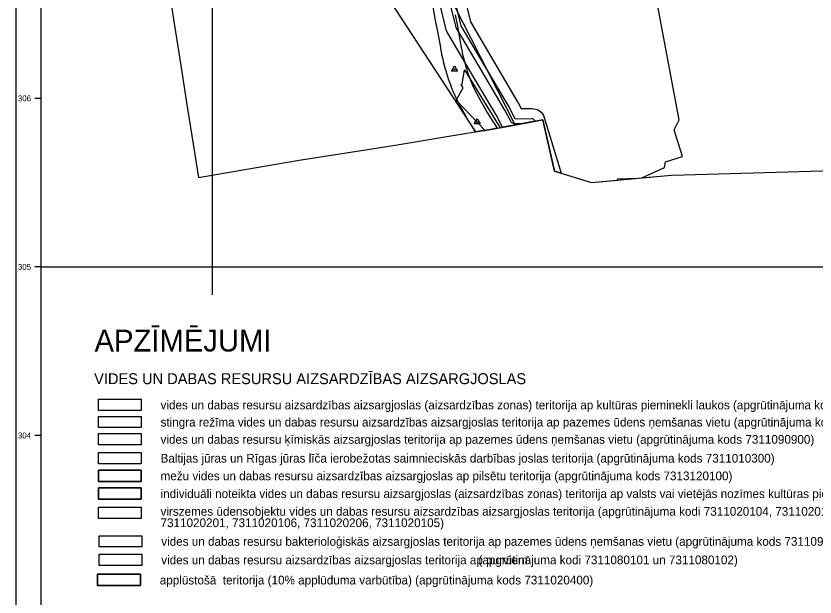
# Model space of a CAD drawing. Extents: x 468834 to 503362, y 294936 to 320859.
# Drawn here: x 468834 to 473572, y 303042 to 306489 of the extents above; entities that cross this region are included whole.
import ezdxf

# ---------------------------------------------------------------- set-up
doc = ezdxf.new("R2010")
doc.units = 0
for name, color, linetype in [('1020108_TIN18_Kemeru_nacionala_parka_teritorija', 7, 'Continuous'), ('7311010300_Baltijas jūras un Rīgas jūras līča ierobežotas saimnieciskās darbības joslas teritorija', 7, 'Continuous'), ('7311020105_dabiskas ūdensteces vides un dabas resursu aizsardzības aizsargjoslas teritorija pilsētās un ciemos', 7, 'Continuous'), ('7311020400_applūstošā (10% applūduma varbūtība) teritorija', 7, 'Continuous'), ('7311080101_vides un dabas resursu aizsardzības aizsargjoslas teritorija ap purvu ar platību no 10 līdz 100 hektāriem', 7, 'Continuous'), ('7311080102_vides un dabas resursu aizsardzības aizsargjoslas teritorija ap purvu ar platību lielāku par 100 hektāriem', 7, 'Continuous'), ('7311090700_stingra režīma vides un dabas resursu aizsardzības aizsargjoslas teritorija ap pazemes ūdens ņemšanas vietu', 7, 'Continuous'), ('7311090800_vides un dabas resursu bakterioloģiskās aizsargjoslas teritorija ap pazemes ūdens ņemšanas vietu', 7, 'Continuous'), ('7311090900_vides un dabas resursu ķīmiskās aizsargjoslas teritorija ap pazemes ūdens ņemšanas vietu', 7, 'Continuous'), ('7312020101_drošības aizsargjoslas teritorija ap gāzesvadu gāzes regulēšanas staciju un gāzes mērīšanas staciju ar gāzesvada diametru līdz 300 milimetriem', 7, 'Continuous'), ('7312030302_ekspluatācijas aizsargjoslas teritorija gar valsts reģionālajiem autoceļiem lauku apvidos', 7, 'Continuous'), ('7312080103_ekspluatācijas aizsargjoslas teritorija gar gāzesvadu ar spiedienu lielāku par 16 megapaskliem', 7, 'Continuous'), ('7313020300_nacionālā parka dabas lieguma zonas teritorija', 7, 'Continuous'), ('7313080100_aizsargājamo ģeoloģisko un ģeomorfoloģisko dabas pieminekļu teritorija', 7, 'Continuous'), ('7313120100_mežu vides un dabas resursu aizsardzības aizsargjoslas ap pilsētu teritorija', 7, 'Continuous'), ('7314020101_vides un dabas resursu aizsardzības aizsargjoslas (aizsardzības zonas) teritorija ap kultūras pieminekli laukos', 7, 'Continuous'), ('7314020201_individuāli noteikta vides un dabas resursu aizsargjoslas (aizsardzības zonas) teritorija ap valsts vai vietējās nozīmes kultūras pieminekli', 7, 'Continuous'), ('aizkrāsjoums-meža aizsargjosla ap pilsētām', 7, 'Continuous'), ('aizkrāsojums_applūstošā teritorija', 7, 'Continuous'), ('Nacionālā parka robeža', 7, 'Continuous'), ('ramis', 7, 'Continuous'), ('Teksts', 7, 'Continuous'), ('Vietējā ģeodēziskā tīkla punkti', 7, 'Continuous')]:
    doc.layers.add(name, color=color, linetype=linetype)

msp = doc.modelspace()

# ---------------------------------------------------------------- linework, layer by layer
at = {"layer": '1020108_TIN18_Kemeru_nacionala_parka_teritorija'}
for p, q in [((469734.9, 306680.4), (469772.2, 306444)), ((469772.2, 306444), (469793.7, 306307.6)), ((469793.7, 306307.6), (469817.3, 306157.4)), ((469817.3, 306157.4), (469845.9, 305976)), ((469845.9, 305976), (469916, 305531.2)), ((471688.4, 305823), (471958.9, 305873.1)), ((471958.9, 305873.1), (472027.8, 305568.2)), ((471496.4, 305790.7), (471595.1, 305806.8)), ((471595.1, 305806.8), (471638.7, 305813.9)), ((471638.7, 305813.9), (471688.4, 305823)), ((471093.9, 305725), (471496.4, 305790.7)), ((470944.5, 305701.4), (471093.9, 305725)), ((470512.3, 305633.4), (470944.5, 305701.4)), ((470374.2, 305609.7), (470512.3, 305633.4)), ((469916, 305531.2), (470374.2, 305609.7)), ((472027.8, 305568.2), (472245.7, 305500)), ((473136.2, 305556.4), (473990.9, 305581.7)), ((472245.7, 305500), (472721.8, 305544.2)), ((472721.8, 305544.2), (472795.3, 305546.3)), ((472795.3, 305546.3), (473136.2, 305556.4))]:
    msp.add_line(p, q, dxfattribs=at)
at = {"layer": '7311010300_Baltijas jūras un Rīgas jūras līča ierobežotas saimnieciskās darbības joslas teritorija'}
msp.add_lwpolyline([(469322.5, 303899.3), (469576.5, 303899.3), (469576.5, 303832.5), (469322.5, 303832.5)], close=True, dxfattribs=at)
at = {"layer": '7311020105_dabiskas ūdensteces vides un dabas resursu aizsardzības aizsargjoslas teritorija pilsētās un ciemos'}
msp.add_lwpolyline([(469322.5, 303575), (469576.5, 303575), (469576.5, 303508.1), (469322.5, 303508.1)], close=True, dxfattribs=at)
at = {"layer": '7311020400_applūstošā (10% applūduma varbūtība) teritorija'}
msp.add_lwpolyline([(469317.9, 303176.5), (469571.9, 303176.5), (469571.9, 303109.6), (469317.9, 303109.6)], close=True, dxfattribs=at)
at = {"layer": '7311080101_vides un dabas resursu aizsardzības aizsargjoslas teritorija ap purvu ar platību no 10 līdz 100 hektāriem'}
msp.add_lwpolyline([(469326.6, 303296), (469580.6, 303296), (469580.6, 303229.1), (469326.6, 303229.1)], close=True, dxfattribs=at)
at = {"layer": '7311080102_vides un dabas resursu aizsardzības aizsargjoslas teritorija ap purvu ar platību lielāku par 100 hektāriem'}
for p, q in [((469734.9, 306680.4), (469772.2, 306444)), ((472766.9, 305872), (472627.8, 306608.1)), ((469772.2, 306444), (469793.7, 306307.6)), ((469793.7, 306307.6), (469817.3, 306157.4)), ((469817.3, 306157.4), (469845.9, 305976)), ((471492.8, 306169.2), (471704.7, 305826)), ((469845.9, 305976), (469916, 305531.2)), ((471704.7, 305826), (471958.9, 305873.1)), ((471958.9, 305873.1), (472027.8, 305568.2)), ((472737.2, 305812.6), (472766.9, 305872)), ((471496.4, 305790.7), (471595.1, 305806.8)), ((471595.1, 305806.8), (471616.5, 305810.3)), ((472785.5, 305654.2), (472737.2, 305812.6)), ((471093.9, 305725), (471496.4, 305790.7)), ((470944.5, 305701.4), (471093.9, 305725)), ((470512.3, 305633.4), (470944.5, 305701.4)), ((470374.2, 305609.7), (470512.3, 305633.4)), ((472679, 305589.9), (472685.6, 305623.8)), ((472685.6, 305623.8), (472785.5, 305654.2)), ((469916, 305531.2), (470374.2, 305609.7)), ((472027.8, 305568.2), (472245.7, 305500)), ((472544.5, 305527.7), (472679, 305589.9)), ((472245.7, 305500), (472544.5, 305527.7))]:
    msp.add_line(p, q, dxfattribs=at)
msp.add_lwpolyline([(471616.5, 305810.3), (471443.1, 305989.9), (471485.1, 306062.4), (471473.2, 306081.3), (471478.7, 306084.8), (471492.8, 306169.2)], dxfattribs=at)
at = {"layer": '7311090700_stingra režīma vides un dabas resursu aizsardzības aizsargjoslas teritorija ap pazemes ūdens ņemšanas vietu'}
msp.add_lwpolyline([(469322.5, 304113.4), (469576.5, 304113.4), (469576.5, 304046.5), (469322.5, 304046.5)], close=True, dxfattribs=at)
at = {"layer": '7311090800_vides un dabas resursu bakterioloģiskās aizsargjoslas teritorija ap pazemes ūdens ņemšanas vietu'}
msp.add_lwpolyline([(469326.6, 303405.7), (469580.6, 303405.7), (469580.6, 303338.9), (469326.6, 303338.9)], close=True, dxfattribs=at)
at = {"layer": '7311090900_vides un dabas resursu ķīmiskās aizsargjoslas teritorija ap pazemes ūdens ņemšanas vietu'}
msp.add_lwpolyline([(469322.5, 304011), (469576.5, 304011), (469576.5, 303944.2), (469322.5, 303944.2)], close=True, dxfattribs=at)
at = {"layer": '7312020101_drošības aizsargjoslas teritorija ap gāzesvadu gāzes regulēšanas staciju un gāzes mērīšanas staciju ar gāzesvada diametru līdz 300 milimetriem'}
msp.add_lwpolyline([(471488.7, 306615.3), (471528.6, 306453.6), (471683.6, 306190.4), (471810.5, 305976.2), (471811.6, 305974.3), (471812.6, 305972.5), (471829.9, 305938.9), (471893.1, 305939.7), (471905.2, 305938.8), (471916.9, 305936.1), (471928.1, 305931.5), (471938.3, 305925.2), (471947.5, 305917.3), (471955.2, 305908), (471961.4, 305897.7), (471965.8, 305886.4), (472065.8, 305556.3), (472027.8, 305568.2), (471958.9, 305873.1), (471718.4, 305828.6), (471716.2, 305832.3), (471680.3, 305901.6), (471554.5, 306114.1), (471393.8, 306386.9), (471388.9, 306396.7), (471385.6, 306407), (471342.9, 306580)], dxfattribs=at)
at = {"layer": '7312030302_ekspluatācijas aizsargjoslas teritorija gar valsts reģionālajiem autoceļiem lauku apvidos'}
msp.add_lwpolyline([(471438.3, 306494.7), (471451.3, 306429), (471451.5, 306428), (471468.3, 306334.6), (471474, 306303.3), (471474.3, 306301.4), (471476.8, 306283.9), (471482.5, 306260.7), (471487.6, 306240.4), (471495.5, 306211.6), (471501.4, 306189.9), (471503.7, 306182.1), (471515.1, 306144.3), (471527.6, 306111.8), (471541.4, 306078), (471554.9, 306049.1), (471580, 306000.3), (471607.2, 305952), (471628.6, 305916), (471661.8, 305862.9), (471672.8, 305845.5), (471687.1, 305822.8), (471638.7, 305813.9), (471623.4, 305811.4), (471595.1, 305806.8), (471559.1, 305801), (471526.5, 305852.9), (471525.8, 305854.1), (471503.7, 305891.3), (471503, 305892.5), (471474.9, 305942.4), (471473.8, 305944.3), (471447.6, 305995.2), (471447.4, 305995.8), (471446.6, 305997.3), (471432, 306028.6), (471430.8, 306031.3), (471416.2, 306067.1), (471415.8, 306068.3), (471402.3, 306103.4), (471401.9, 306104.4), (471400.9, 306107.6), (471388.8, 306147.5), (471386.3, 306156), (471385.9, 306157.5), (471379.7, 306179.9), (471371.6, 306209.4), (471371.3, 306210.8), (471366, 306232), (471359.6, 306258.3), (471358.5, 306263.6), (471355.7, 306283), (471350.2, 306313.3), (471333.5, 306406.2), (471320.5, 306472.1), (471320.3, 306473.3), (471302, 306577.3)], dxfattribs=at)
at = {"layer": '7312080103_ekspluatācijas aizsargjoslas teritorija gar gāzesvadu ar spiedienu lielāku par 16 megapaskliem'}
msp.add_lwpolyline([(471430.3, 306601.4), (471472.4, 306430.7), (471632, 306159.9), (471758.9, 305945.6), (471792.6, 305880.5), (471805.2, 305878.6), (471893.8, 305879.7), (471898.6, 305879), (471902.9, 305876.8), (471906.3, 305873.3), (471908.4, 305869), (471909.9, 305864), (471828.2, 305848.9), (471804.3, 305848.6), (471803.1, 305848.7), (471802, 305848.8), (471780.6, 305851.9), (471777.2, 305852.9), (471774.1, 305854.6), (471771.5, 305857), (471769.5, 305859.9), (471732.8, 305930.7), (471606.1, 306144.6), (471445.4, 306417.4), (471444.5, 306419.3), (471443.8, 306421.4), (471401.1, 306594.3)], dxfattribs=at)
at = {"layer": '7313020300_nacionālā parka dabas lieguma zonas teritorija'}
for p, q in [((469734.9, 306680.4), (469772.2, 306444)), ((469772.2, 306444), (469793.7, 306307.6)), ((469793.7, 306307.6), (469817.3, 306157.4)), ((469817.3, 306157.4), (469845.9, 305976)), ((469845.9, 305976), (469916, 305531.2)), ((471688.4, 305823), (471958.9, 305873.1)), ((471958.9, 305873.1), (472027.8, 305568.2)), ((471496.4, 305790.7), (471595.1, 305806.8)), ((471595.1, 305806.8), (471638.7, 305813.9)), ((471638.7, 305813.9), (471688.4, 305823)), ((471093.9, 305725), (471496.4, 305790.7)), ((470944.5, 305701.4), (471093.9, 305725)), ((470512.3, 305633.4), (470944.5, 305701.4)), ((470374.2, 305609.7), (470512.3, 305633.4)), ((469916, 305531.2), (470374.2, 305609.7)), ((472027.8, 305568.2), (472245.7, 305500)), ((473136.2, 305556.4), (473990.9, 305581.7)), ((472523.5, 305525.8), (472721.8, 305544.2)), ((472721.8, 305544.2), (472795.3, 305546.3)), ((472795.3, 305546.3), (473136.2, 305556.4)), ((472245.7, 305500), (472402.8, 305514.6))]:
    msp.add_line(p, q, dxfattribs=at)
msp.add_lwpolyline([(472402.8, 305514.6), (472401.5, 305521.9), (472523.5, 305525.8)], dxfattribs=at)
at = {"layer": '7313080100_aizsargājamo ģeoloģisko un ģeomorfoloģisko dabas pieminekļu teritorija'}
for p, q in [((471558.2, 305800.8), (471595.1, 305806.8)), ((471595.1, 305806.8), (471638.7, 305813.9)), ((471638.7, 305813.9), (471688.4, 305823)), ((471688.4, 305823), (471793.1, 305842.4))]:
    msp.add_line(p, q, dxfattribs=at)
msp.add_lwpolyline([(471793.1, 305842.4), (471329.7, 306756.6), (471146.8, 306973.4), (470963.4, 307124.4), (470835.1, 307161.1), (470773.7, 307003.7), (471558.2, 305800.8)], dxfattribs=at)
at = {"layer": '7313120100_mežu vides un dabas resursu aizsardzības aizsargjoslas ap pilsētu teritorija'}
msp.add_lwpolyline([(469322.5, 303794.5), (469576.5, 303794.5), (469576.5, 303727.7), (469322.5, 303727.7)], close=True, dxfattribs=at)
at = {"layer": '7314020101_vides un dabas resursu aizsardzības aizsargjoslas (aizsardzības zonas) teritorija ap kultūras pieminekli laukos'}
msp.add_lwpolyline([(469322.5, 304215.3), (469576.5, 304215.3), (469576.5, 304148.4), (469322.5, 304148.4)], close=True, dxfattribs=at)
at = {"layer": '7314020201_individuāli noteikta vides un dabas resursu aizsargjoslas (aizsardzības zonas) teritorija ap valsts vai vietējās nozīmes kultūras pieminekli'}
msp.add_lwpolyline([(469322.5, 303622.1), (469576.5, 303622.1), (469576.5, 303689), (469322.5, 303689), (469322.5, 303622.1)], dxfattribs=at)
msp.add_lwpolyline([(469322.5, 303689), (469576.5, 303689), (469576.5, 303622.1), (469322.5, 303622.1)], close=True, dxfattribs=at)
at = {"layer": 'aizkrāsjoums-meža aizsargjosla ap pilsētām'}
msp.add_lwpolyline([(469322.5, 303727.7), (469576.5, 303727.7), (469576.5, 303794.5), (469322.5, 303794.5), (469322.5, 303727.7)], dxfattribs=at)
at = {"layer": 'aizkrāsojums_applūstošā teritorija'}
msp.add_lwpolyline([(469317.9, 303109.6), (469571.9, 303109.6), (469571.9, 303176.5), (469317.9, 303176.5), (469317.9, 303109.6)], dxfattribs=at)
at = {"layer": 'Nacionālā parka robeža'}
for p, q in [((469734.9, 306680.4), (469772.2, 306444)), ((469772.2, 306444), (469793.7, 306307.6)), ((469793.7, 306307.6), (469817.3, 306157.4)), ((469817.3, 306157.4), (469845.9, 305976)), ((469845.9, 305976), (469916, 305531.2)), ((471688.4, 305823), (471958.9, 305873.1)), ((471958.9, 305873.1), (472027.8, 305568.2)), ((471496.4, 305790.7), (471595.1, 305806.8)), ((471595.1, 305806.8), (471638.7, 305813.9)), ((471638.7, 305813.9), (471688.4, 305823)), ((471093.9, 305725), (471496.4, 305790.7)), ((470944.5, 305701.4), (471093.9, 305725)), ((470512.3, 305633.4), (470944.5, 305701.4)), ((470374.2, 305609.7), (470512.3, 305633.4)), ((469916, 305531.2), (470374.2, 305609.7)), ((472027.8, 305568.2), (472245.7, 305500)), ((473136.2, 305556.4), (473990.9, 305581.7)), ((472245.7, 305500), (472721.8, 305544.2)), ((472721.8, 305544.2), (472795.3, 305546.3)), ((472795.3, 305546.3), (473136.2, 305556.4))]:
    msp.add_line(p, q, dxfattribs=at)
at = {"layer": 'ramis'}
for p, q in [((468983.8, 295086.2), (468983.8, 316660.3)), ((470000, 304835), (470000, 312492.9)), ((468983.8, 306000), (468945.7, 306000)), ((468983.8, 305000), (468945.7, 305000)), ((468983.8, 304000), (468945.7, 304000))]:
    msp.add_line(p, q, dxfattribs=at)
msp.add_lwpolyline([(501073.3, 316810.3), (468833.8, 316810.3), (468833.8, 294936.2), (501073.3, 294936.2)], close=True, dxfattribs=at)
msp.add_lwpolyline([(468983.8, 305000), (500923.3, 305000)], dxfattribs=at)
at = {"layer": 'Vietējā ģeodēziskā tīkla punkti'}
for p, q in [((471415.9, 306161.8), (471433.9, 306193)), ((471433.9, 306193), (471451.9, 306161.8)), ((471451.9, 306161.8), (471415.9, 306161.8)), ((471550.3, 305848.3), (471568.3, 305879.5)), ((471568.3, 305879.5), (471586.3, 305848.3)), ((471586.3, 305848.3), (471550.3, 305848.3))]:
    msp.add_line(p, q, dxfattribs=at)
for centre in [(471433.9, 306172.2), (471568.3, 305858.7)]:
    msp.add_circle(centre, 2, dxfattribs=at)

# ---------------------------------------------------------------- texts
at = {"layer": 'ramis'}
for s, p in [('306', (468845, 305982.6)), ('305', (468845, 304982.6)), ('304', (468845, 303982.6))]:
    msp.add_text(s, height=35, dxfattribs=at).set_placement(p)
at = {"layer": 'Teksts'}
for s, height, p in [('APZĪMĒJUMI', 129.6, (469299.7, 304498.2)), ('VIDES UN DABAS RESURSU AIZSARDZĪBAS AIZSARGJOSLAS', 64.8, (469297.3, 304304.6)), ('vides un dabas resursu aizsardzības aizsargjoslas (aizsardzības zonas) teritorija ap kultūras pieminekli laukos (apgrūtinājuma kods 7314020101)', 51.84, (469691.1, 304155.2)), ('stingra režīma vides un dabas resursu aizsardzības aizsargjoslas teritorija ap pazemes ūdens ņemšanas vietu (apgrūtinājuma kods 7311090700)', 51.84, (469691.1, 304053.3)), ('vides un dabas resursu ķīmiskās aizsargjoslas teritorija ap pazemes ūdens ņemšanas vietu (apgrūtinājuma kods 7311090900)', 51.84, (469691.1, 303951)), ('Baltijas jūras un Rīgas jūras līča ierobežotas saimnieciskās darbības joslas teritorija (apgrūtinājuma kods 7311010300)', 51.84, (469691.1, 303839.3)), ('mežu vides un dabas resursu aizsardzības aizsargjoslas ap pilsētu teritorija (apgrūtinājuma kods 7313120100)', 51.84, (469691.1, 303734.5)), ('individuāli noteikta vides un dabas resursu aizsargjoslas (aizsardzības zonas) teritorija ap valsts vai vietējās nozīmes kultūras pieminekli (apgrūtinājuma kods 7314020201)', 51.84, (469691.1, 303629)), ('virszemes ūdensobjektu vides un dabas resursu aizsardzības aizsargjoslas teritorija (apgrūtinājuma kodi 7311020104, 7311020103, 7311020110, 7311020204, 7311020203,', 51.84, (469691.1, 303523.9)), ('7311020201, 7311020106, 7311020206, 7311020105)', 51.84, (469691.1, 303456.5)), ('vides un dabas resursu bakterioloģiskās aizsargjoslas teritorija ap pazemes ūdens ņemšanas vietu (apgrūtinājuma kods 7311090800)', 51.84, (469695.2, 303345.7)), ('vides un dabas resursu aizsardzības aizsargjoslas teritorija ap purviem', 51.84, (469695.2, 303236)), (' (apgrūtinājuma kodi 7311080101 un 7311080102)', 51.84, (471557.1, 303236)), ('applūstošā  teritorija (10% applūduma varbūtība) (apgrūtinājuma kods 7311020400)', 51.84, (469686.5, 303116.4))]:
    msp.add_text(s, height=height, dxfattribs=at).set_placement(p)

doc.saveas('drawing.dxf')
